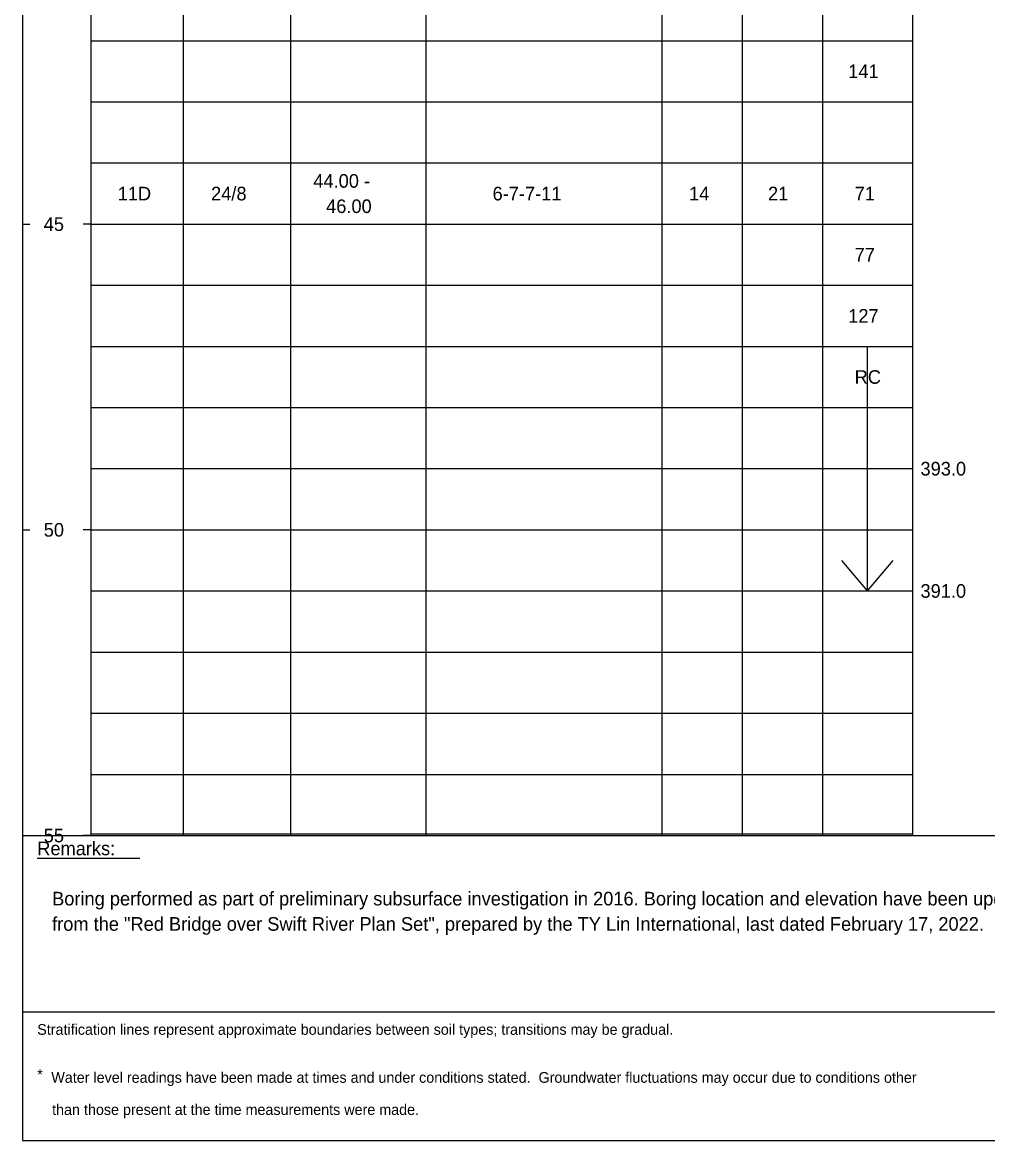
# Model space of a CAD drawing. Extents: x 9422 to 9552, y 6780 to 6860.
# Drawn here: x 9422.45 to 9438.23, y 6787.02 to 6805.31 of the extents above; entities that cross this region are included whole.
import ezdxf

# ---------------------------------------------------------------- set-up
doc = ezdxf.new("R2010")
doc.units = 0
doc.layers.add('7', color=7, linetype='Continuous')

msp = doc.modelspace()

# ---------------------------------------------------------------- linework, layer by layer
at = {"layer": '7'}
for p, q in [((9436.264, 6797.011), (9436.264, 6800.011)), ((9436.264, 6796.011), (9436.264, 6797.011)), ((9436.264, 6796.011), (9435.847, 6796.511)), ((9436.264, 6796.011), (9436.681, 6796.511)), ((9422.692, 6791.642), (9424.37, 6791.642))]:
    msp.add_line(p, q, dxfattribs=at)
for points in [[(9422.449, 6822.038), (9422.449, 6796.983)], [(9423.567, 6822.038), (9423.567, 6796.983)], [(9425.076, 6822.038), (9425.076, 6796.983)], [(9426.831, 6822.038), (9426.831, 6796.983)], [(9429.046, 6822.038), (9429.046, 6796.983)], [(9432.901, 6822.038), (9432.901, 6796.983)], [(9434.213, 6822.038), (9434.213, 6796.983)], [(9435.526, 6822.038), (9435.526, 6796.983)], [(9437.002, 6822.038), (9437.002, 6796.983)], [(9423.567, 6805.011), (9425.076, 6805.011)], [(9425.076, 6805.011), (9426.831, 6805.011)], [(9426.831, 6805.011), (9429.046, 6805.011)], [(9429.046, 6805.011), (9432.901, 6805.011)], [(9432.901, 6805.011), (9434.213, 6805.011)], [(9434.213, 6805.011), (9435.526, 6805.011)], [(9435.526, 6805.011), (9437.002, 6805.011)], [(9423.567, 6804.011), (9425.076, 6804.011)], [(9425.076, 6804.011), (9426.831, 6804.011)], [(9426.831, 6804.011), (9429.046, 6804.011)], [(9429.046, 6804.011), (9432.901, 6804.011)], [(9432.901, 6804.011), (9434.213, 6804.011)], [(9434.213, 6804.011), (9435.526, 6804.011)], [(9435.526, 6804.011), (9437.002, 6804.011)], [(9423.567, 6803.011), (9425.076, 6803.011)], [(9425.076, 6803.011), (9426.831, 6803.011)], [(9426.831, 6803.011), (9429.046, 6803.011)], [(9429.046, 6803.011), (9432.901, 6803.011)], [(9432.901, 6803.011), (9434.213, 6803.011)], [(9434.213, 6803.011), (9435.526, 6803.011)], [(9435.526, 6803.011), (9437.002, 6803.011)], [(9422.449, 6802.011), (9422.571, 6802.011)], [(9423.567, 6802.011), (9423.445, 6802.011)], [(9423.567, 6802.011), (9425.076, 6802.011)], [(9425.076, 6802.011), (9426.831, 6802.011)], [(9426.831, 6802.011), (9429.046, 6802.011)], [(9429.046, 6802.011), (9432.901, 6802.011)], [(9432.901, 6802.011), (9434.213, 6802.011)], [(9434.213, 6802.011), (9435.526, 6802.011)], [(9435.526, 6802.011), (9437.002, 6802.011)], [(9423.567, 6801.011), (9425.076, 6801.011)], [(9425.076, 6801.011), (9426.831, 6801.011)], [(9426.831, 6801.011), (9429.046, 6801.011)], [(9429.046, 6801.011), (9432.901, 6801.011)], [(9432.901, 6801.011), (9434.213, 6801.011)], [(9434.213, 6801.011), (9435.526, 6801.011)], [(9435.526, 6801.011), (9437.002, 6801.011)], [(9423.567, 6800.011), (9425.076, 6800.011)], [(9425.076, 6800.011), (9426.831, 6800.011)], [(9426.831, 6800.011), (9429.046, 6800.011)], [(9429.046, 6800.011), (9432.901, 6800.011)], [(9432.901, 6800.011), (9434.213, 6800.011)], [(9434.213, 6800.011), (9435.526, 6800.011)], [(9435.526, 6800.011), (9437.002, 6800.011)], [(9423.567, 6799.011), (9425.076, 6799.011)], [(9425.076, 6799.011), (9426.831, 6799.011)], [(9426.831, 6799.011), (9429.046, 6799.011)], [(9429.046, 6799.011), (9432.901, 6799.011)], [(9432.901, 6799.011), (9434.213, 6799.011)], [(9434.213, 6799.011), (9435.526, 6799.011)], [(9435.526, 6799.011), (9437.002, 6799.011)], [(9423.567, 6798.011), (9425.076, 6798.011)], [(9425.076, 6798.011), (9426.831, 6798.011)], [(9426.831, 6798.011), (9429.046, 6798.011)], [(9429.046, 6798.011), (9432.901, 6798.011)], [(9432.901, 6798.011), (9434.213, 6798.011)], [(9434.213, 6798.011), (9435.526, 6798.011)], [(9435.526, 6798.011), (9437.002, 6798.011)], [(9422.449, 6797.038), (9422.449, 6792.011)], [(9422.449, 6797.011), (9422.571, 6797.011)], [(9423.567, 6797.011), (9423.445, 6797.011)], [(9423.567, 6797.038), (9423.567, 6792.011)], [(9423.567, 6797.011), (9425.076, 6797.011)], [(9425.076, 6797.038), (9425.076, 6792.011)], [(9425.076, 6797.011), (9426.831, 6797.011)], [(9426.831, 6797.038), (9426.831, 6792.011)], [(9426.831, 6797.011), (9429.046, 6797.011)], [(9429.046, 6797.038), (9429.046, 6792.011)], [(9429.046, 6797.011), (9432.901, 6797.011)], [(9432.901, 6797.038), (9432.901, 6792.011)], [(9432.901, 6797.011), (9434.213, 6797.011)], [(9434.213, 6797.038), (9434.213, 6792.011)], [(9434.213, 6797.011), (9435.526, 6797.011)], [(9435.526, 6797.038), (9435.526, 6792.011)], [(9435.526, 6797.011), (9437.002, 6797.011)], [(9437.002, 6797.038), (9437.002, 6792.011)], [(9423.567, 6796.011), (9425.076, 6796.011)], [(9425.076, 6796.011), (9426.831, 6796.011)], [(9426.831, 6796.011), (9429.046, 6796.011)], [(9429.046, 6796.011), (9432.901, 6796.011)], [(9432.901, 6796.011), (9434.213, 6796.011)], [(9434.213, 6796.011), (9435.526, 6796.011)], [(9435.526, 6796.011), (9437.002, 6796.011)], [(9423.567, 6795.011), (9425.076, 6795.011)], [(9425.076, 6795.011), (9426.831, 6795.011)], [(9426.831, 6795.011), (9429.046, 6795.011)], [(9429.046, 6795.011), (9432.901, 6795.011)], [(9432.901, 6795.011), (9434.213, 6795.011)], [(9434.213, 6795.011), (9435.526, 6795.011)], [(9435.526, 6795.011), (9437.002, 6795.011)], [(9423.567, 6794.011), (9425.076, 6794.011)], [(9425.076, 6794.011), (9426.831, 6794.011)], [(9426.831, 6794.011), (9429.046, 6794.011)], [(9429.046, 6794.011), (9432.901, 6794.011)], [(9432.901, 6794.011), (9434.213, 6794.011)], [(9434.213, 6794.011), (9435.526, 6794.011)], [(9435.526, 6794.011), (9437.002, 6794.011)], [(9423.567, 6793.011), (9425.076, 6793.011)], [(9425.076, 6793.011), (9426.831, 6793.011)], [(9426.831, 6793.011), (9429.046, 6793.011)], [(9429.046, 6793.011), (9432.901, 6793.011)], [(9432.901, 6793.011), (9434.213, 6793.011)], [(9434.213, 6793.011), (9435.526, 6793.011)], [(9435.526, 6793.011), (9437.002, 6793.011)], [(9422.449, 6792.011), (9453.945, 6792.011)], [(9422.449, 6792.011), (9422.571, 6792.011)], [(9422.449, 6792.011), (9422.449, 6787.02)], [(9423.567, 6792.011), (9423.445, 6792.011)], [(9423.567, 6792.038), (9425.076, 6792.038)], [(9423.567, 6792.011), (9425.076, 6792.011)], [(9425.076, 6792.038), (9426.831, 6792.038)], [(9425.076, 6792.011), (9426.831, 6792.011)], [(9426.831, 6792.038), (9429.046, 6792.038)], [(9426.831, 6792.011), (9429.046, 6792.011)], [(9429.046, 6792.038), (9432.901, 6792.038)], [(9429.046, 6792.011), (9432.901, 6792.011)], [(9432.901, 6792.038), (9434.213, 6792.038)], [(9432.901, 6792.011), (9434.213, 6792.011)], [(9434.213, 6792.038), (9435.526, 6792.038)], [(9434.213, 6792.011), (9435.526, 6792.011)], [(9435.526, 6792.038), (9437.002, 6792.038)], [(9435.526, 6792.011), (9437.002, 6792.011)], [(9422.449, 6789.128), (9453.945, 6789.128)], [(9422.449, 6787.02), (9453.945, 6787.02)]]:
    msp.add_lwpolyline(points, dxfattribs=at)

# ---------------------------------------------------------------- texts
for s, height, p in [('141', 0.2228, (9435.949, 6804.399)), ('44.00 -', 0.2228, (9427.205, 6802.606)), ('11D', 0.2228, (9424.007, 6802.399)), ('24/8', 0.2228, (9425.534, 6802.399)), ('6-7-7-11', 0.2228, (9430.135, 6802.399)), ('14', 0.2228, (9433.347, 6802.399)), (' 21', 0.2228, (9434.555, 6802.399)), ('71', 0.2228, (9436.054, 6802.399)), ('46.00', 0.2228, (9427.414, 6802.192)), ('45', 0.2228, (9422.798, 6801.899)), ('77', 0.2228, (9436.054, 6801.399)), ('127', 0.2228, (9435.949, 6800.399)), ('RC', 0.2228, (9436.054, 6799.399)), ('393.0', 0.2228, (9437.13, 6797.899)), ('50', 0.2228, (9422.798, 6796.899)), ('391.0', 0.2228, (9437.13, 6795.899)), ('55', 0.2228, (9422.798, 6791.899)), ('Remarks:', 0.2228, (9422.692, 6791.688)), ('Boring performed as part of preliminary subsurface investigation in 2016. Boring location and elevation have been updated based on interpolation', 0.222801, (9422.935, 6790.867)), ('from the "Red Bridge over Swift River Plan Set", prepared by the TY Lin International, last dated February 17, 2022.', 0.222801, (9422.935, 6790.453)), ('Stratification lines represent approximate boundaries between soil types; transitions may be gradual.', 0.175058, (9422.692, 6788.751)), ('*', 0.175, (9422.692, 6788.015)), (' Water level readings have been made at times and under conditions stated.  Groundwater fluctuations may occur due to conditions other', 0.175058, (9422.857, 6787.966)), ('than those present at the time measurements were made.', 0.17506, (9422.935, 6787.44))]:
    msp.add_text(s, height=height, dxfattribs=at).set_placement(p)

doc.saveas('drawing.dxf')
